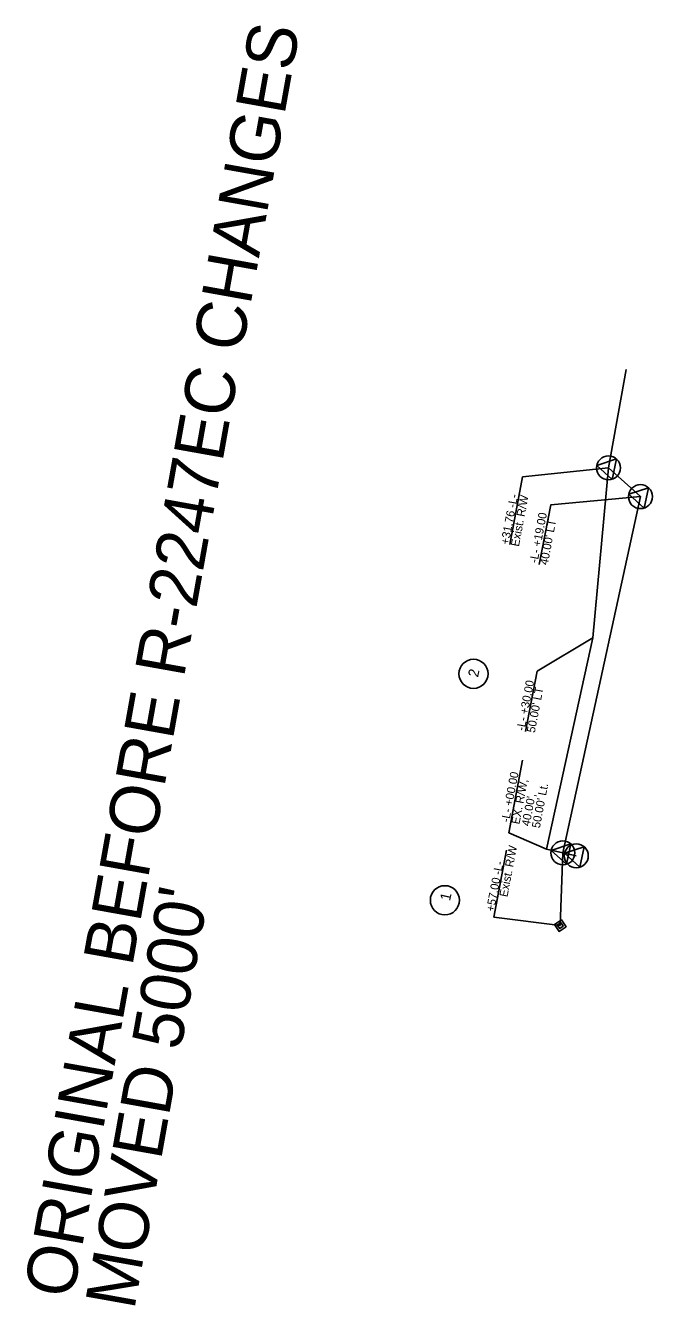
# Model space of a CAD drawing. Extents: x 1610947 to 1617684, y 899814 to 904658.
# Drawn here: x 1610947 to 1611324, y 900438 to 901206 of the extents above; entities that cross this region are included whole.
import ezdxf

# ---------------------------------------------------------------- set-up
doc = ezdxf.new("R2010")
doc.units = 0
for name, color, linetype in [('Prop Conc 1ft 6in Curb and Gutter', 7, 'Continuous'), ('Prop EOT Dash', 7, 'Continuous'), ('Prop Hatching', 7, 'Continuous'), ('Prop ROW Marker CELL', 7, 'Continuous'), ('Prop ROW RW Lines', 7, 'Continuous'), ('Prop ROW Station Offsets', 7, 'Continuous'), ('Scratch_Level_3', 7, 'Continuous'), ('Scratch_Level_8', 7, 'Continuous'), ('Typical Terminator CELL', 7, 'Continuous')]:
    doc.layers.add(name, color=color, linetype=linetype)

msp = doc.modelspace()

# ---------------------------------------------------------------- linework, layer by layer
at = {"layer": 'Prop Conc 1ft 6in Curb and Gutter'}
for p, q in [((1611297.27, 900940.77), (1611307.82, 900999.87)), ((1611254.44, 900818.75), (1611287.76, 900838.69)), ((1611254.44, 900818.75), (1611247.44, 900782.48))]:
    msp.add_line(p, q, dxfattribs=at)
at = {"layer": 'Prop EOT Dash'}
for points in [[(1611264.74, 900666.55), (1611268.94, 900669.42), (1611271.81, 900665.21), (1611267.6, 900662.34)], [(1611266.5, 900666.21), (1611268.61, 900667.65), (1611270.04, 900665.54), (1611267.94, 900664.11)]]:
    msp.add_lwpolyline(points, close=True, dxfattribs=at)
at = {"layer": 'Prop Hatching'}
for centre in [(1611216.13, 900817.1), (1611198.93, 900681.08)]:
    msp.add_circle(centre, 8.75, dxfattribs=at)
at = {"layer": 'Prop ROW Marker CELL'}
for p, q in [((1611297.27, 900940.77), (1611297.27, 900940.77)), ((1611316.48, 900923.52), (1611316.48, 900923.52)), ((1611269.86, 900709.54), (1611269.86, 900709.54)), ((1611277.92, 900707.79), (1611277.92, 900707.79)), ((1611268.27, 900665.88), (1611268.27, 900665.88))]:
    msp.add_line(p, q, dxfattribs=at)
for points in [[(1611299.5, 900933.91), (1611290.23, 900942.26), (1611302.09, 900946.13)], [(1611318.7, 900916.66), (1611309.43, 900925.02), (1611321.3, 900928.89)], [(1611272.08, 900702.68), (1611262.82, 900711.04), (1611274.68, 900714.91)], [(1611280.14, 900700.92), (1611270.88, 900709.28), (1611282.74, 900713.15)]]:
    msp.add_lwpolyline(points, close=True, dxfattribs=at)
for centre in [(1611297.27, 900940.77), (1611316.48, 900923.52), (1611269.86, 900709.54), (1611277.92, 900707.79)]:
    msp.add_circle(centre, 7.2, dxfattribs=at)
at = {"layer": 'Prop ROW RW Lines'}
for p, q in [((1611316.48, 900923.52), (1611297.27, 900940.77)), ((1611269.86, 900709.54), (1611316.48, 900923.52)), ((1611295.44, 900920.93), (1611295.46, 900921)), ((1611277.92, 900707.79), (1611269.86, 900709.54))]:
    msp.add_line(p, q, dxfattribs=at)
at = {"layer": 'Prop ROW Station Offsets'}
for p, q in [((1611297.27, 900940.77), (1611245.63, 900935.4)), ((1611245.63, 900935.4), (1611237.93, 900894.83)), ((1611245.58, 900765.17), (1611237.32, 900721.68)), ((1611260.09, 900711.67), (1611237.32, 900721.68))]:
    msp.add_line(p, q, dxfattribs=at)
msp.add_lwpolyline([(1611316.48, 900923.52), (1611262.54, 900918.58), (1611255.69, 900882.81)], dxfattribs=at)
at = {"layer": 'Scratch_Level_3'}
for p, q in [((1611287.76, 900838.69), (1611297.27, 900940.77)), ((1611260.09, 900711.67), (1611287.76, 900838.69)), ((1611260.09, 900711.67), (1611269.86, 900709.54))]:
    msp.add_line(p, q, dxfattribs=at)
at = {"layer": 'Scratch_Level_8'}
msp.add_line((1611235.93, 900711.15), (1611228.28, 900670.89), dxfattribs=at)
msp.add_lwpolyline([(1611228.28, 900670.89), (1611268.27, 900665.88)], dxfattribs=at)
at = {"layer": 'Typical Terminator CELL'}
msp.add_line((1611268.27, 900665.88), (1611269.86, 900709.54), dxfattribs=at)

# ---------------------------------------------------------------- texts
at = {"layer": 'Prop Conc 1ft 6in Curb and Gutter'}
for s, height, rotation, p in [('ORIGINAL BEFORE R-2247EC CHANGES', 30, 79.85906, (1610975.24, 900441.09)), ('-L- +30.00', 5, 79.07272, (1611246.82, 900782.6)), ("50.00' LT", 5, 79.07272, (1611252.96, 900781.41)), ("MOVED 5000'", 30, 79.85906, (1611012.15, 900434.48))]:
    msp.add_text(s, height=height, rotation=rotation, dxfattribs=at).set_placement(p)
at = {"layer": 'Prop Hatching'}
for s, p in [('2', (1611218.81, 900814.7)), ('1', (1611201.99, 900680.41))]:
    msp.add_text(s, height=6.25, rotation=77.71667, dxfattribs=at).set_placement(p)
at = {"layer": 'Prop ROW Station Offsets'}
for s, p in [('+31.76 -L-', (1611237.27, 900894.41)), ('Exist. R/W', (1611243.41, 900893.25)), ('-L- +19.00', (1611254.59, 900883.34)), ("40.00' LT", (1611260.73, 900882.17)), ('-L- +00.00', (1611237.57, 900727.61)), ('EX. R/W,', (1611243.71, 900726.45)), ("50.00' Lt.", (1611255.99, 900724.12)), ("40.00',", (1611249.85, 900725.28))]:
    msp.add_text(s, height=5, rotation=79.24937, dxfattribs=at).set_placement(p)
at = {"layer": 'Scratch_Level_8'}
for s, p in [('Exist. R/W', (1611236.52, 900682.76)), ('+57.00 -L-', (1611228.49, 900673.97))]:
    msp.add_text(s, height=5, rotation=79.24937, dxfattribs=at).set_placement(p)

doc.saveas('drawing.dxf')
